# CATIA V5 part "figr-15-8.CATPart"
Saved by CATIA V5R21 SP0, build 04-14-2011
Part number: Part1
Bounding box of the stored display mesh (mm): x -50 to 50, y -32.5 to 33.5, z -52 to 1
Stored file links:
  D:\CATIA V5R21 E-RESOURCES\CATIA-V5R21\catia-v5r21-prt\c15-catia-v5r20-prt\c15-catia-v5r21-figr-15-8.CATPart
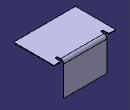
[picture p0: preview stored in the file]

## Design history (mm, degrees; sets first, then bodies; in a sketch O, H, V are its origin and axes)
SheetMetalParameters1: Thickness 1, BendRadius 4, KFactor 0.475772 {= log(min(100,max(20*SheetMetalParameters1.BendRadius,SheetMetalParameters1.Thickness)/SheetMetalParameters1.Thickness))/log(100)/2}, ReliefRadialLength 4, ReliefAxialLength 4, MinimumBendRadius 0
Body1 (main body)
  Sketch1 on xy-plane, origin (0, 0, 0), H (1, 0, 0), V (0, 1, 0)
    line L1 (-50, 32.5) -> (50, 32.5)
    line L2 (50, 32.5) -> (50, -32.5)
    line L3 (50, -32.5) -> (-50, -32.5)
    line L4 (-50, -32.5) -> (-50, 32.5)
    length L1 = 100
    length L2 = 65
    horizontal: L1 H, L3 H
    vertical: L2 V, L4 V
    symmetry: L4 L2 V, L1 L3 H
  Wall1: Thickness 1, Profile Sketch1
  d_NewWallOnEdge1: NewWallOnEdge_Edge edge [face of Wall1 | face of Wall1], NewWallOnEdge_Length 53, NewWallOnEdge_HeightLimitOffset 0, NewWallOnEdge_WidthOffset1 -15, NewWallOnEdge_WidthOffset2 -15, NewWallOnEdge_Angle 90, NewWallOnEdge_BendRadiusValue 4 {= SheetMetalParameters1.BendRadius}, NewWallOnEdge_BendTable SheetMetalParameters1, KFacteur 0.475772 {= log(min(100,max(20*d_NewWallOnEdge1.Radius,SheetMetalParameters1.Thickness)/SheetMetalParameters1.Thickness))/log(100)/2}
